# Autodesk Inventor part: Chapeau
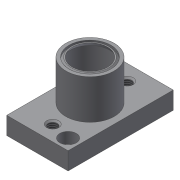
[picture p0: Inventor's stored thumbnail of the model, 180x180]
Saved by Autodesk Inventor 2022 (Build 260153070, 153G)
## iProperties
Created: 2018-06
Part Number: Chapeau
Material: Aluminium 6061
Document SubType Name: Modeling
Designer: Fabian Perrée
Density: 2.7 g/cm^3
Appearance: Générique
Mass: 26.5554 g
Surface Area: 66.9581 cm^2
Volume: 9.83534 cm^3
Author: Fabian Perrée
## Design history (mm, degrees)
sketch "Esquisse1"
  geometry: L1 (-14, 24)-(14, 24); L2 (14, 24)-(14, -24); L3 (14, -24)-(-14, -24); L4 (-14, -24)-(-14, 24); L5 (-14, 24)-(14, -24); L6 (14, 24)-(-14, -24); 1 further point
  constraints: 12 end point, 2 midpoint, 2 parallel, 1 horizontal, 1 perpendicular
  dimensions: "d0" = 28 distance of L2.end L3.end; "d1" = 48 distance of L1.end L2.end
extrude "Extrusion1" new body sketch "Esquisse1" distance "d2" = 8; taper "d3" = 0 deg
sketch "Esquisse2"
  geometry: L1 (0, 0)-(8, 0); L2 (8, -24)-(8, 24) reference; L3 (26, -11)-(26, -9.5); L4 (26, -9.5)-(25, -9.5); L5 (25, -9.5)-(26, -8.5); L6 (26, -8)-(24.268, -9); L7 (24.268, -9)-(8, -9); L8 (8, -9)-(8, -11); L9 (26, -11)-(8, -11); L10 (26, -8.5)-(26, -8); L11 (8, -9)-(2.5, -9); L12 (2.5, -9)-(2.5, -11.5); L13 (2.5, -11.5)-(0, -11.5); L14 (0, 24)-(0, -24) reference; L15 (0, -11.5)-(0, 0); L16 (8, -9)-(8, 0); L17 (8, 0)-(26, 0)
  constraints: 30 end point, 5 point on line, 4 horizontal, 4 perpendicular, 2 collinear, 2 vertical, 1 midpoint
  dimensions: "d4" = 18 distance from line of L2 L17.end; "d5" = 1.5 distance of L3.start L3.end; "d6" = 1 distance of L3.end L4.end; "d7" = 45 deg angle of L4 L5; "d8" = 150 deg angle of L7 L6; "d9" = 22 diameter of L9 L1; "d10" = 16 diameter of L6.start L1; "d11" = 18 diameter of L7 L1; "d12" = 23 diameter of L13 L1; "d13" = 18 diameter of L11 L1; "d14" = 2.5 distance of L12.end L13.end
revolve "Révolution1" stored, may be unused: angle "d15" = 90 deg
revolve "Révolution2" stored, may be unused: angle "d16" = 90 deg
sketch "Esquisse3"
  geometry: L1 (14, -24)-(14, 24) reference; L2 (-14, -24)-(14, -24) reference; L3 (-14, 24)-(-14, -24) reference; L4 (14, 24)-(-14, 24) reference; 3 further points
  dimensions: "d17" = 5 distance from line of L1 point (9, -19); "d18" = 5 distance from line of L2 point (9, -19); "d19" = 5 distance from line of L3 point (-9, 19); "d20" = 5 distance from line of L4 point (-9, 19)
hole "Perçage1" sketch "Esquisse3" at (-9, 19), (9, -19) diameter "d21" = 4.5; stored, may be unused: countersink angle "d25" = 90 deg, drill point angle "d27" = 118 deg; dims "d22" = 6, "d23" = 7.5, "d24" = 5, "d26" = 8
sketch "Esquisse4"
  geometry: L1 (-14, 24)-(-14, -24) reference; L2 (-14, -24)-(14, -24) reference; L3 (14, 24)-(-14, 24) reference; 3 further points
  dimensions: "d28" = 14 distance from line of L1 point (0, -17); "d29" = 7 distance from line of L2 point (0, -17); "d30" = 14 distance from line of L1 point (0, 17); "d31" = 7 distance from line of L3 point (0, 17)
hole "Perçage2" sketch "Esquisse4" at (0, -17), (0, 17) diameter "d32" = 4.134; stored, may be unused: countersink angle "d36" = 90 deg, drill point angle "d38" = 118 deg; dims "d33" = 10, "d34" = 5.5, "d35" = 5, "d37" = 14.2
feature "Scission1"
node "Solide1"
